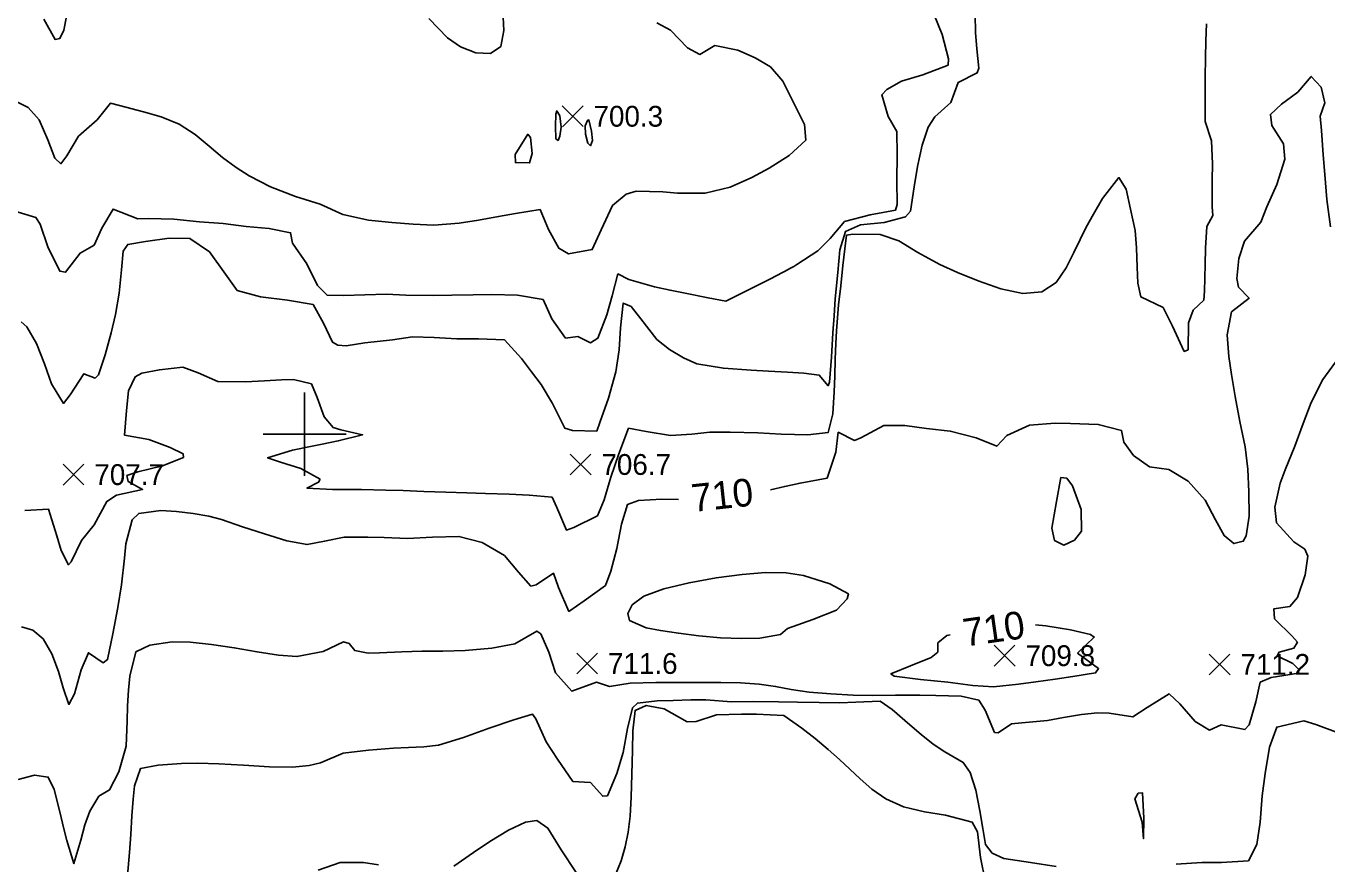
# Model space of a CAD drawing. Extents: x 2566079 to 2571326, y 424054 to 426896.
# Drawn here: x 2567799 to 2568737, y 424690 to 425294 of the extents above; entities that cross this region are included whole.
import ezdxf

# ---------------------------------------------------------------- set-up
doc = ezdxf.new("R2010")
doc.units = 0
for name, color, linetype in [('Contour_ADS_Label_Major', 7, 'Continuous'), ('Contour_ADS_Major', 7, 'Continuous'), ('Contour_ADS_Minor', 7, 'Continuous'), ('Contour_ADS_Spot_Elevation', 7, 'Continuous'), ('Contour_ADS_Tick', 7, 'Continuous')]:
    doc.layers.add(name, color=color, linetype=linetype)

# ---------------------------------------------------------------- blocks, each defined once
blk = doc.blocks.new('S890')
at = {"layer": 'Contour_ADS_Tick'}
for p, q in [((0, -0.5), (0, 0.5)), ((-0.5, 0), (0.5, 0))]:
    blk.add_line(p, q, dxfattribs=at)
blk = doc.blocks.new('S750')
at = {"layer": 'Contour_ADS_Spot_Elevation'}
for p, q in [((-0.5, 0.498), (0.5, -0.498)), ((-0.498, -0.5), (0.498, 0.5))]:
    blk.add_line(p, q, dxfattribs=at)

msp = doc.modelspace()

# ---------------------------------------------------------------- linework, layer by layer
at = {"layer": 'Contour_ADS_Major'}
for points in [[(2567830.13, 425311.01), (2567826.49, 425291.4), (2567823.6, 425285.41), (2567820.05, 425284.63), (2567811.99, 425299.22)], [(2568739.53, 425149.51), (2568736.86, 425169.21), (2568735.39, 425187.27), (2568734.18, 425201.4), (2568733.01, 425218.9), (2568732.07, 425229.2), (2568735.37, 425238.95), (2568732.8, 425250.1), (2568725.69, 425257.91), (2568715.97, 425246.53), (2568704.12, 425238.03), (2568696.24, 425230.55), (2568697.18, 425222.53), (2568705.73, 425209.28), (2568706.6, 425198.19), (2568700.84, 425180.06), (2568693.59, 425163.83), (2568689.44, 425152.81), (2568677.52, 425139.23), (2568673.54, 425126.7), (2568672.01, 425112.35), (2568673.24, 425105.93), (2568680.92, 425098.06), (2568668.09, 425088.23), (2568665.08, 425071.62), (2568666.34, 425055.91), (2568668.28, 425043.1), (2568670.8, 425027.29), (2568674.16, 425009.05), (2568677.93, 424991), (2568680.06, 424974.73), (2568680.7, 424958.5), (2568680.99, 424940.99), (2568678.79, 424926.63), (2568676.65, 424922.84), (2568669.88, 424921.17), (2568662.84, 424926.97), (2568656.63, 424938.36), (2568649.09, 424952.52), (2568636.9, 424966.1), (2568623.01, 424974.49), (2568609.17, 424976.41), (2568597.51, 424984.66), (2568590.59, 424994.16), (2568588.91, 425002.56), (2568572.07, 425007.05), (2568552.18, 425007.76), (2568541.14, 425007.89), (2568522.67, 425006.59), (2568506.29, 424999.04), (2568498.92, 424991.27), (2568484.14, 424997.49), (2568465.38, 425002.29), (2568448.24, 425004.03), (2568432.57, 425006.2), (2568417.64, 425006.27), (2568400.87, 424997.3), (2568396.39, 424995.54), (2568384.64, 425001.45), (2568382.98, 424986.99), (2568376.8, 424968.43), (2568357.19, 424964.73), (2568346.11, 424962.34), (2568335.85, 424959.96)], [(2568269.56, 424952.83), (2568257.46, 424953.17), (2568240.61, 424952.1), (2568232.72, 424949.25), (2568228.41, 424935.15), (2568224.96, 424917.54), (2568220.84, 424901.21), (2568216.98, 424890.97), (2568201.6, 424879.76), (2568190.52, 424872.27), (2568183, 424889.57), (2568179.42, 424899.76), (2568167, 424891.41), (2568163.17, 424890.55), (2568154.27, 424900.49), (2568144.03, 424912.57), (2568127.89, 424922.01), (2568111.26, 424926.26), (2568092.14, 424925.68), (2568074.09, 424924.87), (2568057.38, 424925.53), (2568045.44, 424925.68), (2568028.58, 424925.74), (2568014.37, 424922.84), (2568001.79, 424920.48), (2567987.08, 424923.15), (2567971.15, 424928.07), (2567955.27, 424933.14), (2567940.05, 424938.53), (2567930.83, 424940.95), (2567919.61, 424942.92), (2567907.59, 424944.31), (2567896.38, 424945), (2567880.45, 424942.86), (2567875.69, 424938.38), (2567871.11, 424921.08), (2567870.04, 424910.53), (2567867.97, 424891.33), (2567865.29, 424875.1), (2567861.6, 424856.04), (2567857.87, 424837.58), (2567854.85, 424835.28), (2567844.06, 424842.43), (2567838.82, 424830.23), (2567834.15, 424812.8), (2567830.04, 424805.2), (2567825.96, 424817.24), (2567822.53, 424829.03), (2567817.77, 424841.75), (2567811.57, 424852.39), (2567803.97, 424858.67), (2567795.75, 424861.19)], [(2568526.78, 424862.65), (2568534.26, 424861.97), (2568552.03, 424858.9), (2568566.46, 424855.51), (2568569.23, 424853.8), (2568557.17, 424842.21), (2568572.4, 424831.02), (2568570.15, 424827.87), (2568553.88, 424825.26), (2568541.09, 424823.43), (2568527.25, 424821.45), (2568514.55, 424819.69), (2568496.67, 424817.93), (2568481.64, 424818.88), (2568463.79, 424821.33), (2568443.91, 424823.17), (2568425, 424825.58), (2568422.68, 424827.31), (2568436.69, 424833.07), (2568451.66, 424838.96), (2568456.54, 424842.87), (2568456.48, 424849.58), (2568463.08, 424854.85), (2568465.48, 424855.45)]]:
    msp.add_lwpolyline(points, dxfattribs=at)
for points in [[(2568183.92, 425214.86), (2568182.68, 425211.82), (2568181.11, 425213.03), (2568180.73, 425222.09), (2568181.13, 425230.62), (2568181.76, 425233.08), (2568183.89, 425229.51), (2568184.83, 425221.4), (2568183.92, 425214.86)], [(2568202.48, 425216.39), (2568202.2, 425222.34), (2568203.91, 425226.29), (2568204.93, 425226.57), (2568206.85, 425218.39), (2568207.4, 425211.65), (2568206.03, 425208.01), (2568204.08, 425209.89), (2568202.48, 425216.39)]]:
    msp.add_lwpolyline(points, close=True, dxfattribs=at)
at = {"layer": 'Contour_ADS_Minor'}
for points in [[(2568089.52, 425299.83), (2568103.09, 425285.78), (2568112.35, 425279.27), (2568123.43, 425274.9), (2568134.07, 425274.37), (2568141.4, 425279.5), (2568143.6, 425291.05), (2568142.82, 425305.57)], [(2568254, 425296.54), (2568263.75, 425291.21), (2568276.1, 425278.52), (2568284.79, 425273.82), (2568295.66, 425280.26), (2568312.28, 425276.78), (2568324.88, 425271.34), (2568335.85, 425264.75), (2568344.75, 425254.56), (2568352.86, 425238.22), (2568360.3, 425223.27), (2568361.38, 425212.07), (2568349.37, 425200.86), (2568334.84, 425191.9), (2568322.28, 425185.17), (2568306.88, 425178.12), (2568288.85, 425173.84), (2568268.88, 425173.76), (2568258.27, 425174.69), (2568238.91, 425175.13), (2568231.68, 425173.17), (2568221.88, 425165.01), (2568213.75, 425147.42), (2568207.39, 425133.16), (2568190.14, 425130.09), (2568183.28, 425134.1), (2568175.85, 425147.68), (2568169.7, 425161.93), (2568152.09, 425159.19), (2568139.8, 425156.93), (2568125.21, 425154.35), (2568111.51, 425152.19), (2568093.08, 425150.73), (2568078.17, 425151.37), (2568062.91, 425152.56), (2568045.98, 425154.35), (2568027.45, 425158.41), (2568011.15, 425165.92), (2567993.33, 425171.39), (2567975.39, 425178.37), (2567960.01, 425186.26), (2567950.58, 425192.22), (2567940.81, 425199.47), (2567931.13, 425207.76), (2567920.99, 425216.12), (2567909.6, 425223.42), (2567896.66, 425228.79), (2567883.83, 425232.49), (2567866.48, 425236.87), (2567859.91, 425238.61), (2567850.49, 425226.68), (2567836.86, 425214.85), (2567828.46, 425200.71), (2567824.32, 425194.96), (2567819.91, 425198.91), (2567814.8, 425212.31), (2567808.51, 425226.59), (2567800.78, 425235.59), (2567784.44, 425243.7)], [(2568483.37, 425302.54), (2568483.69, 425289.67), (2568484.56, 425277.93), (2568486.01, 425263.88), (2568484.82, 425260.43), (2568471.14, 425253.66), (2568465.9, 425239.23), (2568454.2, 425228.9), (2568449.47, 425221.36), (2568445.19, 425208.48), (2568441.71, 425192.91), (2568439.37, 425178.36), (2568436.66, 425160.86), (2568433.17, 425156.62), (2568417.82, 425152.63), (2568400.8, 425151.06), (2568389.84, 425146.16), (2568385.82, 425133), (2568384.31, 425116.63), (2568382.56, 425097.5), (2568381.66, 425085.34), (2568380.85, 425072.98), (2568379.85, 425055.63), (2568378.43, 425037.44), (2568377.52, 425034.9), (2568370.98, 425042.59), (2568359.94, 425044.11), (2568348.19, 425044.74), (2568334.38, 425045.44), (2568321.79, 425046.15), (2568301.86, 425047.58), (2568282.75, 425050.85), (2568273.16, 425055.13), (2568263.02, 425061.12), (2568253.94, 425068.26), (2568242.28, 425083.09), (2568235.39, 425092.02), (2568229.68, 425094.59), (2568227.75, 425076.65), (2568226.66, 425060.95), (2568224.33, 425045), (2568219, 425025.93), (2568212.89, 425008.45), (2568210.62, 425002.25), (2568193.19, 425002.79), (2568187.61, 425004.32), (2568178.78, 425022.07), (2568170.5, 425035.79), (2568163.63, 425045.08), (2568156.21, 425054.53), (2568144.03, 425068.12), (2568125.23, 425068.71), (2568109.62, 425068.76), (2568093.32, 425069.67), (2568077.67, 425070.18), (2568063.27, 425068.11), (2568043.46, 425065.84), (2568029.89, 425063.82), (2568023.9, 425064.1), (2568019.97, 425066.31), (2568013.52, 425080.07), (2568006.13, 425093.59), (2567987.74, 425096.63), (2567968.16, 425098.99), (2567951.39, 425103.56), (2567942.91, 425115.32), (2567931.31, 425131.42), (2567917.15, 425141.19), (2567902.38, 425141.3), (2567885.22, 425138.89), (2567872.51, 425136.8), (2567869.27, 425132.03), (2567867.94, 425118.57), (2567866.2, 425101.61)], [(2568650.12, 425295.82), (2568649.77, 425283.6), (2568649.52, 425271.29), (2568649.32, 425257.5), (2568649.16, 425243.83), (2568649.16, 425225.5), (2568653.68, 425211.62), (2568654.46, 425194.88), (2568654.29, 425183.07), (2568654.21, 425163.88), (2568654.66, 425157.66), (2568650.42, 425149.81), (2568649.53, 425134.09), (2568649.17, 425122.39), (2568648.72, 425103.1), (2568648.23, 425096.54), (2568640.66, 425089.49), (2568637.11, 425080.21), (2568636.94, 425060.89), (2568634.17, 425059.75), (2568625.69, 425077.83), (2568618.81, 425091.42), (2568602.9, 425098.95), (2568600.6, 425108.89), (2568600.17, 425120.48), (2568599.7, 425134.26), (2568598.81, 425146.82), (2568595.35, 425162.25), (2568592.2, 425176.57), (2568587.08, 425184.98), (2568575.11, 425169.82), (2568568.72, 425158.73), (2568563.5, 425149.17), (2568559.02, 425140.43), (2568554.5, 425130.92), (2568549.11, 425119.84), (2568541.82, 425109.39), (2568531.57, 425102.57), (2568517.79, 425101.48), (2568501.82, 425104.83), (2568485.51, 425110.47), (2568470.54, 425116.53), (2568457.85, 425122.25), (2568441.95, 425130.93), (2568428.42, 425139.51), (2568414.8, 425143.88), (2568395.27, 425144.16), (2568390.7, 425143.61), (2568389.44, 425133.54), (2568388.07, 425121.57), (2568386.43, 425106.98), (2568384.95, 425093.26), (2568383.37, 425074.45), (2568382.96, 425065.45), (2568382.56, 425054.21), (2568382.13, 425041.92), (2568381.69, 425030.5), (2568380.69, 425014.73), (2568377.49, 425001.34), (2568362.64, 424999.66), (2568343.6, 425000.07), (2568326.64, 425000.88), (2568306.71, 425001.41), (2568292.12, 425001.39), (2568279.07, 425000.09), (2568263.73, 424999.12), (2568246.24, 425002), (2568233.49, 425004.32), (2568226.58, 424985.88), (2568220.7, 424969.04), (2568215.85, 424952.59), (2568211.01, 424941.21), (2568194.13, 424932.83), (2568188.72, 424930.94), (2568181.74, 424947.16), (2568178.39, 424954.7), (2568161.92, 424956.16), (2568147.45, 424956.71), (2568130.4, 424957.19), (2568116.95, 424957.62), (2568101.7, 424958.16), (2568085.91, 424958.76), (2568071.01, 424959.33), (2568058.46, 424959.76), (2568040.97, 424960.07), (2568031.75, 424960.12), (2568020, 424960.24), (2568001.61, 424961.14), (2568010.06, 424965.35), (2568011.1, 424967.57)], [(2568453.73, 425302.24), (2568459.67, 425288.11), (2568464.21, 425270.7), (2568463.91, 425266.09), (2568445.78, 425258.99), (2568430.24, 425254.46), (2568419.68, 425248.58), (2568416.04, 425244.56), (2568420.69, 425229), (2568426.87, 425218.34), (2568427.2, 425201.4), (2568426.92, 425182.88), (2568427.14, 425165.69), (2568425.87, 425161.44), (2568407.67, 425158.24), (2568389.25, 425153.39), (2568378.85, 425141.03), (2568369.97, 425132.24), (2568354.78, 425122.3)], [(2568336.78, 425112.56), (2568320.95, 425104.62), (2568303.69, 425096), (2568290.89, 425098.27), (2568274.38, 425101.64), (2568263.48, 425103.85), (2568252.25, 425106.26), (2568233.73, 425111.46), (2568225.83, 425115.54), (2568221.6, 425099.72), (2568217.89, 425086.08), (2568211.29, 425069.23), (2568206.08, 425065.95), (2568196.96, 425070.47), (2568188.17, 425069.21), (2568178.23, 425083.11), (2568171.94, 425097.15), (2568153.53, 425100.21), (2568134.91, 425100.7), (2568121.48, 425100.48), (2568106.22, 425100.28), (2568092.56, 425100.11), (2568072.91, 425100.18), (2568059.07, 425101.01), (2568043.38, 425100.53), (2568028.2, 425099.9), (2568016.18, 425100.23), (2568009.14, 425107.23), (2568001.5, 425122.75), (2567991.3, 425137.73), (2567989.83, 425145.24), (2567974.31, 425148.34), (2567957.94, 425149.85), (2567941.32, 425151.86), (2567924.15, 425153.22), (2567905.78, 425154.92), (2567887.39, 425155.61), (2567879.71, 425155.24), (2567861.91, 425162.28), (2567853.75, 425148.48), (2567848.29, 425136.36), (2567838.04, 425130.6), (2567827.67, 425116.8), (2567823.38, 425117.63), (2567814.77, 425135.16), (2567809.32, 425151.4), (2567806.28, 425156.17), (2567787.98, 425161.69)], [(2567866.2, 425101.61), (2567863.67, 425086.24), (2567860.43, 425073.08), (2567856.24, 425057.16), (2567851.4, 425042.87), (2567849.04, 425040.47), (2567840.77, 425043.64), (2567830.96, 425028.42), (2567826.16, 425022.21), (2567817.57, 425036.22), (2567812.37, 425050.64), (2567806.72, 425065.41), (2567799.73, 425077.53), (2567795.54, 425081.01)], [(2568743.29, 425052.04), (2568734, 425039.54), (2568725.59, 425022.75), (2568719.74, 425007.73), (2568713.97, 424991.44), (2568706.81, 424974.38), (2568703.35, 424964.77), (2568699.44, 424947.41), (2568700.65, 424936.17), (2568713.02, 424922.5), (2568721, 424917.24), (2568723.27, 424912.05), (2568721.36, 424898.59), (2568715.68, 424882.35), (2568710.27, 424875.8), (2568698.78, 424874.18), (2568699.1, 424866.93), (2568711.98, 424854.51), (2568715.74, 424850.18), (2568713.2, 424845.82), (2568702.57, 424842.88), (2568701.2, 424840.28), (2568712.43, 424834.67), (2568716.73, 424830.45), (2568716.46, 424827.68), (2568696.73, 424824.67), (2568688.97, 424821.19), (2568685.79, 424807.18), (2568680.98, 424790.59), (2568677.82, 424787), (2568660.74, 424790.58), (2568652.39, 424786.64), (2568641.88, 424792.93), (2568631.03, 424805.59), (2568623.26, 424812.74), (2568607.37, 424802.88), (2568596.99, 424796.34), (2568580.11, 424798.81), (2568571.7, 424799.12), (2568560.06, 424797.87), (2568547.14, 424795.73), (2568535.51, 424793.68), (2568517.04, 424791.9), (2568509.5, 424791.2), (2568500.09, 424784.8), (2568497.44, 424785.02), (2568490.63, 424801.05), (2568486.1, 424808.21), (2568473.41, 424811.13), (2568454.93, 424811.64), (2568443.55, 424811.85), (2568425.9, 424811.82), (2568409.36, 424811.65), (2568395.5, 424811.97), (2568379.28, 424812.75), (2568363.66, 424814.11), (2568350.79, 424816.07), (2568339.49, 424818.17), (2568327.72, 424819.87), (2568314.15, 424820.76), (2568300.14, 424821.04), (2568287.74, 424821.02), (2568270.64, 424820.97), (2568253.17, 424820.92), (2568234.56, 424820.48)], [(2568011.1, 424967.57), (2567997.19, 424975.35), (2567982.59, 424979.96), (2567973.33, 424983.05), (2567991.31, 424988.56), (2568004.16, 424991.16), (2568012.65, 424992.94), (2568024.23, 424995.21), (2568041.8, 424999.65), (2568026.14, 425003.19), (2568020.52, 425004.91), (2568014.06, 425012.46), (2568008.99, 425026.39), (2568004.93, 425036.25), (2567991.98, 425039.44), (2567983.33, 425039.22), (2567970.98, 425038.51), (2567957.3, 425037.74), (2567937.5, 425038), (2567923.34, 425044.31), (2567912.06, 425048.43), (2567895.24, 425046.44), (2567882.72, 425044.04), (2567877.75, 425041.47), (2567873.05, 425031.26), (2567871.48, 425017.17), (2567870.23, 424999.26), (2567887.71, 424996.15), (2567902.94, 424990.39), (2567912.38, 424985.93), (2567912.62, 424983.25), (2567897.41, 424977.1), (2567879.71, 424972.85), (2567871.9, 424970.18), (2567872.86, 424965.81), (2567883.15, 424960.17), (2567864.42, 424956.06), (2567857.49, 424951.59), (2567848.24, 424934.6), (2567839.01, 424923.46), (2567831.58, 424907.92), (2567829.7, 424905.87), (2567824.48, 424916.24), (2567821.31, 424926.81), (2567815.43, 424945.85), (2567798.25, 424945.1)], [(2568234.56, 424820.48), (2568219.73, 424818.05), (2568210.34, 424821.29), (2568192.61, 424814.64), (2568180.95, 424828.08), (2568175.95, 424842.85), (2568170.16, 424856.2), (2568167.42, 424858.11), (2568151.47, 424848.87), (2568134.85, 424845.79), (2568115.73, 424844.03), (2568099.67, 424843.54), (2568084.53, 424843.68), (2568070.13, 424843.16), (2568053.88, 424842.33), (2568045.83, 424842.23), (2568036.13, 424843.97), (2568032.08, 424849.02), (2568028.06, 424850.33), (2568013.34, 424843.34), (2567994.47, 424839.64), (2567981.08, 424840.63), (2567965.72, 424843.09), (2567949.29, 424846), (2567932.76, 424848.45), (2567917.38, 424850.03), (2567904.47, 424850.43), (2567888.42, 424847.86), (2567878.26, 424843.09), (2567873.85, 424825.5), (2567872.99, 424815.37), (2567872.4, 424804.06), (2567872.01, 424793.06), (2567871.4, 424775.01), (2567866.08, 424756.7), (2567859.33, 424743.57), (2567851.66, 424738.96), (2567845.06, 424728.32), (2567841.64, 424718.35), (2567838.55, 424707.33), (2567833.69, 424690.46), (2567828.44, 424707.03), (2567826.14, 424716.56), (2567823.69, 424726.88), (2567819.42, 424743.87), (2567815.17, 424752.77), (2567805.22, 424754.29), (2567793.41, 424751.17)], [(2568541.83, 424688.36), (2568523.23, 424691.2), (2568504.04, 424694.1), (2568495.74, 424697.87), (2568490.87, 424704.26), (2568488.91, 424715.7), (2568486.84, 424728.57), (2568483.81, 424743.44), (2568479.78, 424756.07), (2568474.75, 424763.43), (2568461.42, 424770.92), (2568453.15, 424776.45), (2568444.49, 424783.39), (2568436.26, 424790.47), (2568423.52, 424801.43), (2568414.96, 424807.66), (2568397.28, 424806.76), (2568385.5, 424806.42), (2568370.84, 424806.49), (2568355.34, 424806.8), (2568341.52, 424807.13), (2568323.86, 424807.25), (2568307.83, 424807.11), (2568289.11, 424808.5), (2568278.35, 424808.4), (2568265.76, 424808.08), (2568254.1, 424807.76), (2568239.85, 424806.12), (2568236.34, 424802.66), (2568232.85, 424787.9), (2568229.69, 424770.52), (2568225, 424755.42), (2568218.22, 424739.21), (2568214.87, 424738.95), (2568206.12, 424748.86), (2568193.44, 424749.65), (2568182.28, 424765.72), (2568174.05, 424778.18), (2568166.67, 424794.82), (2568164.14, 424798.26), (2568150.71, 424794.09), (2568132.98, 424788.03), (2568114.5, 424781.4), (2568096.52, 424775.87), (2568085.99, 424774.65), (2568074.85, 424774.14), (2568064.01, 424773.76), (2568045.93, 424772.14), (2568027.85, 424769.95), (2568011.49, 424763.19), (2568003.23, 424761.06), (2567991.16, 424759.9), (2567974.69, 424760.18), (2567956.02, 424761.31), (2567938.05, 424762.44), (2567923.08, 424762.89), (2567911.16, 424762.72), (2567894.37, 424761.46), (2567881.74, 424759.11), (2567877.37, 424746.44), (2567876.42, 424736.8), (2567875.52, 424724.87), (2567874.6, 424711.4), (2567873.71, 424698.35), (2567872.31, 424681.74)], [(2568490.8, 424676.94), (2568487.28, 424694.85), (2568485.11, 424713.28), (2568481.32, 424720.2), (2568462.06, 424725.37), (2568446.81, 424727.77), (2568431.64, 424731.44), (2568418.99, 424737.13), (2568408.8, 424744.19), (2568400.37, 424751.58), (2568392.96, 424758.54), (2568385.65, 424765.37), (2568377.5, 424772.63), (2568368.01, 424780.55), (2568358.48, 424788.1), (2568345.51, 424797.13), (2568325.75, 424798.2), (2568314.92, 424798.06), (2568296.86, 424797.67), (2568282.14, 424792.77), (2568275.77, 424792.56), (2568259.23, 424802.08), (2568246.28, 424804.45), (2568238.25, 424800.83), (2568236.63, 424786.15), (2568236.33, 424771.86), (2568235.93, 424754.95), (2568235.38, 424738.44), (2568234.58, 424724.63), (2568233.26, 424713.08), (2568231.13, 424702.64), (2568228.07, 424692.54), (2568221.78, 424676.61)], [(2568745.2, 424784.67), (2568729.03, 424790.6), (2568720.36, 424793.26), (2568700.87, 424788.83), (2568695.65, 424774.3), (2568692.38, 424755.4), (2568690.37, 424739.26), (2568688.86, 424720.33), (2568686.44, 424704.27), (2568680.37, 424692.37), (2568661.02, 424691.21), (2568646.81, 424691.3), (2568628.19, 424689.96)], [(2568195.84, 424683.95), (2568184.98, 424700.31), (2568175.26, 424715.87), (2568167.49, 424721.49), (2568159.26, 424720.34), (2568147.06, 424714.6), (2568133.44, 424706.34), (2568121.69, 424698.47), (2568107.56, 424688.48)], [(2568053.16, 424689.6), (2568042.34, 424691.16), (2568025.51, 424691.14), (2568009.73, 424685.6)]]:
    msp.add_lwpolyline(points, dxfattribs=at)
for points in [[(2568164.13, 425202.38), (2568162.84, 425213.85), (2568160.86, 425216.23), (2568151.82, 425201.55), (2568151.99, 425195.87), (2568162.2, 425195.58), (2568164.13, 425202.38)], [(2568549.38, 424968.38), (2568545.11, 424968.69), (2568542.01, 424951.49), (2568538.57, 424932.17), (2568540.48, 424923.38), (2568547.42, 424919.96), (2568554.94, 424923.61), (2568560.01, 424930.09), (2568559.7, 424945.63), (2568553.46, 424962.78), (2568549.38, 424968.38)], [(2568348.12, 424859.87), (2568366.35, 424866.47), (2568383.35, 424873.26), (2568391.05, 424881.28), (2568392.01, 424885), (2568378.69, 424892.11), (2568359.68, 424898.1), (2568347.09, 424900.08), (2568332.22, 424900.32), (2568315.33, 424898.96), (2568296.73, 424896.38), (2568277.15, 424892.89), (2568258.84, 424888.51), (2568244.46, 424883.17), (2568236, 424876.99), (2568232.95, 424870.84), (2568234.17, 424865.74), (2568246.19, 424860.32), (2568256.54, 424858.59), (2568269.47, 424856.61), (2568284.17, 424854.63), (2568299.68, 424853.18), (2568314.92, 424852.64), (2568328.26, 424852.97), (2568343.06, 424855.63), (2568348.12, 424859.87)], [(2568601.02, 424741.28), (2568598.58, 424737.18), (2568603.7, 424720.33), (2568604.86, 424708.34), (2568604.94, 424723.12), (2568604.01, 424741.54), (2568601.02, 424741.28)]]:
    msp.add_lwpolyline(points, close=True, dxfattribs=at)
msp.add_arc((2568145.43, 425487.68), 421.11, 297.02586, 299.81076, dxfattribs=at)

# ---------------------------------------------------------------- block references
at = {"layer": 'Contour_ADS_Spot_Elevation', "xscale": 15, "yscale": 15}
for p in [(2568193.24, 425229.22), (2568198.95, 424978.18), (2567833.38, 424970.87), (2568504.64, 424840.33), (2568203.66, 424834.71), (2568659.62, 424834.04)]:
    msp.add_blockref('S750', p, dxfattribs=at)
at = {"layer": 'Contour_ADS_Tick', "xscale": 60, "yscale": 60}
msp.add_blockref('S890', (2568000, 425000), dxfattribs=at)

# ---------------------------------------------------------------- texts
at = {"layer": 'Contour_ADS_Label_Major'}
for rotation, p in [(6.14071, (2568279.86, 424943.87)), (8.04945, (2568476.07, 424846.84))]:
    msp.add_text('710', height=20, rotation=rotation, dxfattribs=at).set_placement(p)
at = {"layer": 'Contour_ADS_Spot_Elevation'}
for s, p in [('700.3', (2568208.24, 425221.72)), ('706.7', (2568213.95, 424970.68)), ('707.7', (2567848.38, 424963.37)), ('709.8', (2568519.64, 424832.83)), ('711.6', (2568218.66, 424827.21)), ('711.2', (2568674.62, 424826.54))]:
    msp.add_text(s, height=15, dxfattribs=at).set_placement(p)

doc.saveas('drawing.dxf')
